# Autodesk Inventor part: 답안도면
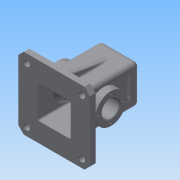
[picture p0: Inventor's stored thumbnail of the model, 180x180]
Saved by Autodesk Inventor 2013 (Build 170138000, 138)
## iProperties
Created: 2016-02
Part Number: 답안도면
Material: 일반
Document SubType Name: Modeling
Designer: Administrator
Density: 1 g/cm^3
Author: Administrator
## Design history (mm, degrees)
sketch "스케치1"
  geometry: L1 (35, 0)-(-35, 0); L2 (-35, 0)-(-35, 120); L3 (-35, 120)-(35, 120); L4 (35, 120)-(35, 0); 2 further points
  constraints: 8 end point, 2 coincident, 2 parallel, 1 horizontal, 1 midpoint, 1 perpendicular
  dimensions: "d0" = 70 distance of L2.end L3.end; "d3" = 120 distance of L3.end L1.start
extrude "돌출1" new body sketch "스케치1" stored distance "d4" = 70; taper "d5" = 0 deg
sketch "스케치2"
  geometry: L1 (-30, 30)-(100, 30); L2 (100, 30)-(100, -100); L3 (100, -100)-(-30, -100); L4 (-30, -100)-(-30, 30); 3 further points
  constraints: 8 end point, 2 midpoint, 2 parallel, 1 horizontal, 1 horizontal alignment, 1 perpendicular, 1 vertical alignment
  dimensions: "d6" = 130 distance of L1.end L2.end; "d8" = 130 distance of L1.start L1.end
extrude "돌출2" join sketch "스케치2" distance "d9" = 10; taper "d10" = 0 deg
node "작업 평면1"
sketch "스케치3"
  geometry: L1 (-30, -120)-(100, -120) reference; C1 r 27.5 at (35, -65); 2 further points
  constraints: 1 centre point, 1 midpoint, 1 vertical alignment
  dimensions: "d12" = 55 diameter of C1; "d14" = 55 distance from line of L1 C1.centre
extrude "돌출3" join sketch "스케치3" distance "d15" = 96; taper "d16" = 0 deg
hole "구멍1" diameter "d19" = 32; stored, may be unused: countersink angle "d23" = 90 deg, drill point angle "d25" = 0 deg; dims "d17" = 10, "d18" = 10, "d20" = 6, "d21" = 4, "d22" = 2, "d24" = 8
sketch "스케치4"
  geometry: L1 (-35, 10)-(-35, 120) reference; L2 (-35, 120)-(35, 120) reference; L3 (35, 120)-(35, 10) reference; L4 (30, 0)-(30, 115); L5 (30, 115)-(-30, 115); L6 (-30, 115)-(-30, 0); L7 (65, 0)-(-65, 0) reference; L8 (-30, 0)-(30, 0); 1 further point
  constraints: 8 end point, 2 point on line, 1 collinear
  dimensions: "d26" = 5 distance between parallel lines of L5 L2; "d27" = 5 distance between parallel lines of L4 L3; "d28" = 5 distance between parallel lines of L1 L6
extrude "돌출4" cut sketch "스케치4" stored distance "d29" = 60; taper "d30" = 0 deg
sketch "스케치5"
  geometry: L1 (-30, 0)-(-30, 115) reference; L2 (30, 115)-(30, 0) reference; L3 (48, 71)-(30, 71) reference; L4 (48, 39)-(30, 39) reference; L5 (-30, 71)-(-48, 71) reference; L6 (-30, 39)-(-48, 39) reference; L7 (-30, 82.5)-(-23, 75.5); L8 (-23, 75.5)-(-23, 71); L9 (-23, 71)-(-30, 71); L10 (-68.044, 55)-(90.6, 55); L11 (30, 82.5)-(23, 75.5); L12 (23, 75.5)-(23, 71); L13 (23, 71)-(30, 71); L14 (30, 0)-(-30, 0) reference; L15 (30, 71)-(30, 82.5); L16 (-30, 71)-(-30, 82.5); 1 further point
  constraints: 18 end point, 4 parallel, 2 perpendicular, 2 point on line, 1 collinear, 1 horizontal
  dimensions: "d31" = 55 distance between parallel lines of L14 L10; "d32" = 135 deg angle of L7 L1; "d33" = 135 deg angle of L11 L2 (derived); "d34" = 7 distance between parallel lines of L1 L8; "d35" = 7 distance between parallel lines of L12 L2; "d36" = 55 diameter of L7.start L10; "d37" = 55 diameter of L11.start L10
revolve "회전1" sketch "스케치5" stored, may be unused: angle "d38" = 90 deg
fillet "모깎기1" dims "d39" = 3
fillet "모깎기2" dims "d40" = 3
fillet "모깎기3" dims "d41" = 8
fillet "모깎기4" dims "d42" = 8
sketch "스케치7"
  geometry: L1 (-27, 120)-(27, 120) reference; L2 (0, 120)-(0, 138.989); L3 (-20, 120)-(-18.237, 130); L4 (-18.237, 130)-(0, 130); L5 (-30, 112)-(-30, 60.22) reference; L6 (-20, 120)-(0, 120); 1 further point
  constraints: 8 end point, 2 perpendicular, 2 point on line, 1 collinear, 1 midpoint, 1 vertical alignment
  dimensions: "d44" = 40 diameter of L3.start L2; "d46" = 10 distance between parallel lines of L1 L4; "d47" = 10 deg angle of L5 L3
revolve "회전2" sketch "스케치7" stored, may be unused: angle "d48" = 90 deg
hole "구멍2" diameter "d51" = 28; stored, may be unused: countersink angle "d55" = 90 deg, drill point angle "d57" = 0 deg; dims "d49" = 10, "d50" = 10, "d52" = 6, "d53" = 4, "d54" = 2, "d56" = 4
hole "구멍3" diameter "d60" = 21; stored, may be unused: countersink angle "d64" = 90 deg, drill point angle "d66" = 0 deg; dims "d58" = 10, "d59" = 10, "d61" = 6, "d62" = 4, "d63" = 2, "d65" = 4
sketch "스케치8" dims "d67" = 45
  geometry: C1 r 27.5 at (0, 0) reference; 3 further points
  constraints: 2 vertical alignment, 1 coincident, 2 other
hole "구멍4" sketch "스케치8" at (0, 22.5) diameter "d69" = 3.459; stored, may be unused: countersink angle "d73" = 90 deg, drill point angle "d75" = 118 deg; dims "d70" = 8, "d71" = 4, "d72" = 2, "d74" = 10
sketch "스케치10" dims "d79" = 45
  geometry: C1 r 27.5 at (0, 0) reference; 3 further points
  constraints: 2 vertical alignment, 1 coincident, 2 other
hole "구멍5" sketch "스케치10" at (0, 22.5) diameter "d81" = 3.459; stored, may be unused: countersink angle "d85" = 90 deg, drill point angle "d87" = 118 deg; dims "d82" = 8, "d83" = 4, "d84" = 2, "d86" = 10
fillet "모깎기5" dims "d91" = 3
chamfer "모따기1" distance "d92" = 10; stored, may be unused: second distance "d93" = 2, angle "d94" = 45 deg
sketch "스케치11"
  geometry: L1 (-15, 85)-(85, 85); L2 (85, 85)-(85, -15); L3 (85, -15)-(-15, -15); L4 (-15, -15)-(-15, 85); C1 r 6 at (-15, 85); C2 r 6 at (85, 85); C3 r 6 at (-15, -15); C4 r 6 at (85, -15); 3 further points
  constraints: 8 end point, 4 centre point, 4 coincident, 2 midpoint, 2 parallel, 1 horizontal, 1 horizontal alignment, 1 perpendicular, 1 vertical alignment
  dimensions: "d95" = 100 distance of L1.end L2.end; "d97" = 100 distance of L1.start L1.end; "d98" = 12 diameter of C1; "d99" = 12 diameter of C2; "d100" = 12 diameter of C4; "d101" = 12 diameter of C3
extrude "돌출5" cut sketch "스케치11" stored distance "d102" = 60; taper "d103" = 0 deg
sketch "스케치12"
  geometry: L1 (10, 35)-(112, 35) reference; L2 (10, -55)-(10, 55) reference; L3 (112, -35)-(10, -35) reference; L4 (95.069, 35)-(10, 50); L5 (95.069, -35)-(10, -50); L6 (0, 65)-(10, 65) reference; L7 (10, 65)-(10, 55) reference; L8 (10, 56)-(10, 44) reference; L9 (10, -65)-(0, -65) reference; 1 further point
  constraints: 4 end point, 3 point on line, 1 midpoint
  dimensions: "d104" = 15 distance from line of L4.end L6; "d105" = 15 distance from line of L9 L5.end; "d106" = 10 deg angle of L4 L6; "d107" = 10 deg angle of L5 L9
extrude "돌출6" join sketch "스케치12" stored distance "d108" = 10; taper "d109" = 0 deg
fillet "모깎기8" dims "d112" = 3
fillet "모깎기9" dims "d113" = 3
fillet "모깎기10" dims "d114" = 3
fillet "모깎기11" dims "d115" = 3
fillet "모깎기12" dims "d116" = 3
chamfer "모따기2" distance "d117" = 1; stored, may be unused: second distance "d118" = 2, angle "d119" = 45 deg
chamfer "모따기3" distance "d120" = 1; stored, may be unused: second distance "d121" = 2, angle "d122" = 45 deg
sketch "스케치14"
  geometry: L1 (18.237, 75)-(-18.237, 75) reference; 3 further points
  constraints: 1 midpoint, 1 vertical alignment, 1 other
  dimensions: "d123" = 30 distance from line of point (0, 45) L1
feature "엠보싱1" sketch "스케치14" dims "d124" = 0.5, "d125" = 0
fillet "모깎기13" dims "d126" = 0.5
fillet "모깎기14" dims "d127" = 0.5
fillet "모깎기15" dims "d128" = 0.5
node "솔리드1"
pattern_circular "원형 패턴1" dims angle "d77" = 360 deg
pattern_circular "원형 패턴2" dims angle "d89" = 360 deg
other parameters: "d11" = 13
